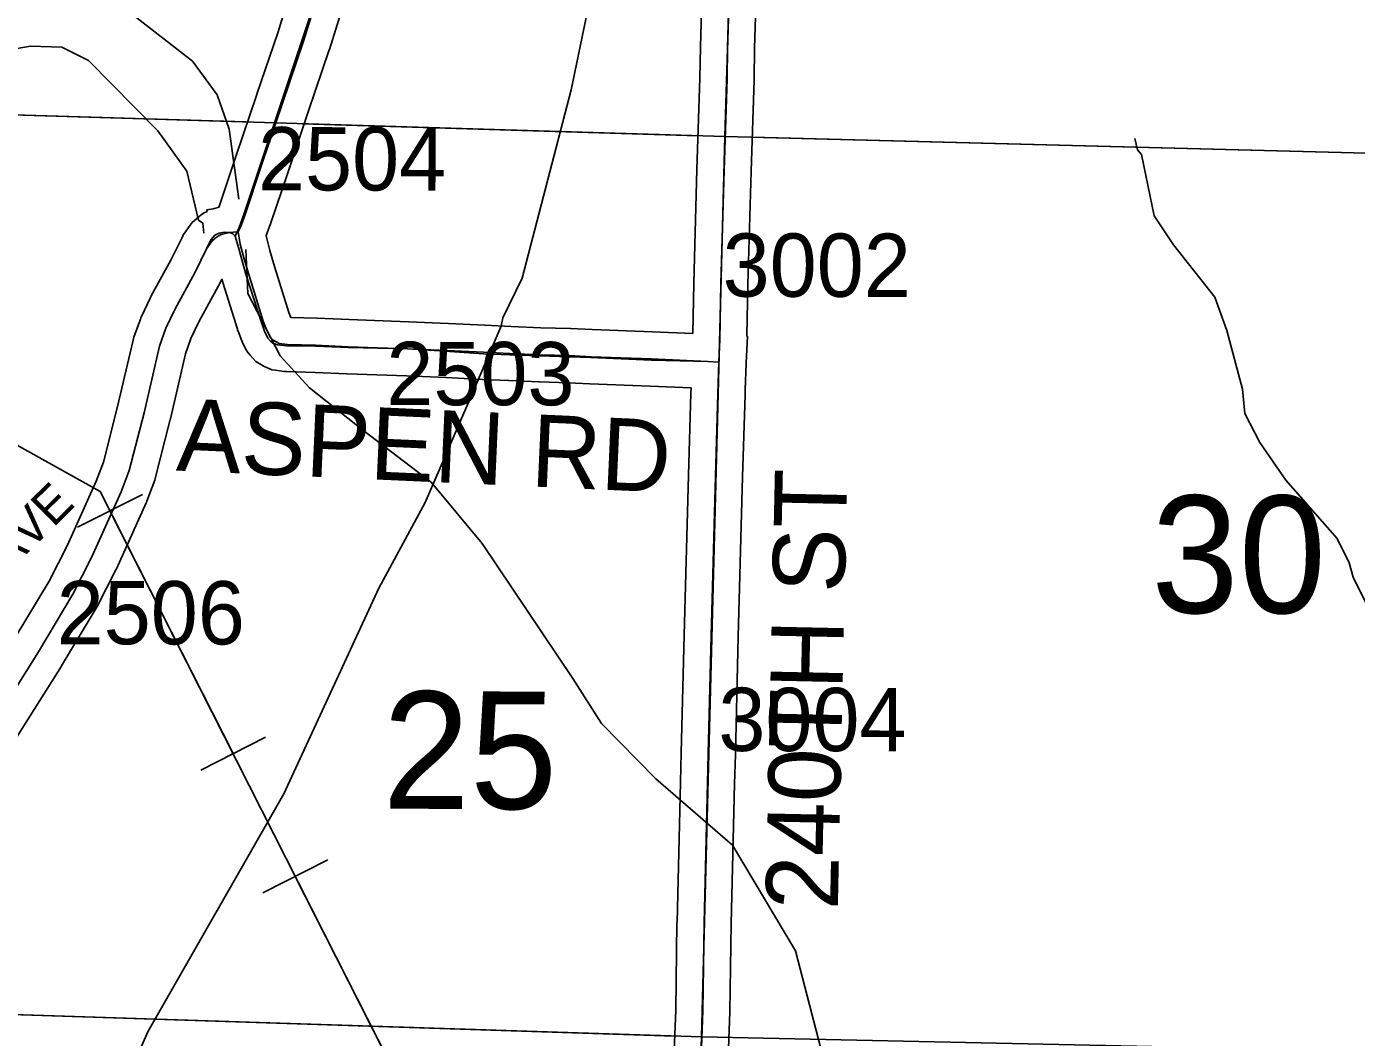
# Model space of a CAD drawing. Extents: x -132.8 to -73.3, y -60 to -26.
# Drawn here: x -116.845 to -115.373, y -55.44 to -54.321 of the extents above; entities that cross this region are included whole.
import ezdxf

# ---------------------------------------------------------------- set-up
doc = ezdxf.new("R2010")
doc.units = 0
for name, color, linetype in [('tdCoHydroRiver', 7, 'Continuous'), ('tdCoPipe', 7, 'Continuous'), ('tdCoRRCL', 7, 'Continuous'), ('tdCoSecRdNmbr', 7, 'Continuous'), ('tdCoSecRdTxt', 7, 'Continuous'), ('tdCoSecRteBand', 7, 'Continuous'), ('tdCoSecRteCL', 7, 'Continuous'), ('tdCoSectLine', 7, 'Continuous'), ('tdCoSectLinePart', 7, 'Continuous'), ('tdCoSectNmbr', 7, 'Continuous'), ('tdCoSurfAsphalt', 7, 'Continuous'), ('tdCoSurfGravel', 7, 'Continuous'), ('tdCoTwpBndryShd', 7, 'Continuous')]:
    doc.layers.add(name, color=color, linetype=linetype)

msp = doc.modelspace()

# ---------------------------------------------------------------- linework, layer by layer
at = {"layer": 'tdCoHydroRiver'}
for points in [[(-116.2762, -53.9828), (-116.2765, -53.9939), (-116.2719, -53.9987), (-116.2692, -54.0177), (-116.2646, -54.0226), (-116.2509, -54.105), (-116.2463, -54.1114), (-116.2384, -54.1731), (-116.2338, -54.178), (-116.2243, -54.2398), (-116.2262, -54.3123), (-116.2424, -54.3908), (-116.2966, -54.5992), (-116.3182, -54.6429), (-116.32, -54.6523), (-116.3553, -54.735), (-116.4039, -54.8474), (-116.4552, -54.9423), (-116.5604, -55.17), (-116.7107, -55.4328), (-116.7224, -55.4593)], [(-116.6489, -54.5492), (-116.6502, -54.5382), (-116.6548, -54.5349), (-116.6677, -54.4809), (-116.6997, -54.4359), (-116.7766, -54.3582), (-116.8062, -54.3433), (-116.8409, -54.3424), (-116.982, -54.3672), (-117.0585, -54.3936), (-117.1383, -54.4295), (-117.159, -54.4368), (-117.2551, -54.4342)], [(-115.1864, -55.1387), (-115.221, -55.1347), (-115.2539, -55.1228), (-115.2725, -55.1097), (-115.297, -55.0807), (-115.3084, -55.0331), (-115.3144, -55.0187), (-115.3603, -54.9639), (-115.3768, -54.9303), (-115.3812, -54.9144), (-115.3947, -54.8873), (-115.4515, -54.8227), (-115.4804, -54.781), (-115.4969, -54.749), (-115.4994, -54.7221), (-115.5167, -54.657), (-115.53, -54.6203), (-115.5759, -54.5624), (-115.5972, -54.5303), (-115.6112, -54.4621), (-115.6158, -54.4572), (-115.6187, -54.4445)]]:
    msp.add_lwpolyline(points, dxfattribs=at)
at = {"layer": 'tdCoPipe'}
for p, q in [((-116.7169, -54.8385), (-116.7888, -54.8749)), ((-116.5806, -55.1073), (-116.6524, -55.1437)), ((-116.5118, -55.243), (-116.5838, -55.2795))]:
    msp.add_line(p, q, dxfattribs=at)
for points in [[(-115.7327, -56.7093), (-116.3792, -55.5939), (-116.7637, -54.8353), (-118.1151, -54.0815), (-118.6092, -53.8056), (-119.7966, -53.496), (-120.031, -53.2709)], [(-116.6166, -55.1255), (-116.7528, -54.8567)], [(-116.4115, -55.5301), (-116.5478, -55.2613)]]:
    msp.add_lwpolyline(points, dxfattribs=at)
at = {"layer": 'tdCoRRCL'}
for points in [[(-117.7743, -53.0804), (-117.6699, -53.3151), (-117.6198, -53.3905), (-117.4718, -53.5238), (-117.421, -53.5756), (-117.4, -53.6156), (-117.379, -53.7218), (-117.416, -53.9307), (-117.4181, -54.0111), (-117.3859, -54.1067), (-117.3433, -54.1677), (-117.2827, -54.2056), (-117.2233, -54.2292), (-116.8722, -54.2637), (-116.7827, -54.2802), (-116.7328, -54.3036), (-116.6616, -54.3591), (-116.6342, -54.3961), (-116.621, -54.4343), (-116.6103, -54.5119)], [(-116.6023, -54.5673), (-116.6004, -54.6163), (-116.5643, -54.6851), (-116.5321, -54.7206), (-116.4718, -54.768), (-116.3975, -54.8251), (-116.3409, -54.8929), (-116.2406, -55.0422), (-116.2087, -55.092), (-116.1487, -55.1535), (-116.0638, -55.2267), (-115.9943, -55.3437), (-115.9584, -55.4819), (-115.9294, -55.5821), (-115.9004, -55.6807), (-115.8417, -55.7911), (-115.8098, -55.8393), (-115.7844, -55.8936), (-115.6201, -56.1329), (-115.346, -56.5172), (-115.1794, -56.6996)]]:
    msp.add_lwpolyline(points, dxfattribs=at)
at = {"layer": 'tdCoSecRteBand'}
for points in [[(-116.1079, -54.6606), (-116.1068, -54.6047), (-116.1068, -54.6046), (-116.1068, -54.6044), (-116.1032, -54.4789), (-116.1032, -54.4789), (-116.1032, -54.4788), (-116.0999, -54.3778), (-116.0994, -54.3432), (-116.0993, -54.343), (-116.0993, -54.3428), (-116.0959, -54.2263)], [(-116.0359, -54.2281), (-116.0394, -54.3444), (-116.0399, -54.379), (-116.0399, -54.3793), (-116.04, -54.3795), (-116.0433, -54.4807), (-116.0468, -54.606), (-116.0479, -54.6629), (-116.0478, -54.6629), (-116.0478, -54.6634), (-116.0474, -54.6634), (-116.0488, -54.6931), (-116.0497, -54.7229), (-116.0497, -54.7229), (-116.0499, -54.7282), (-116.0527, -54.8191), (-116.0574, -54.9958), (-116.0606, -55.1263), (-116.0606, -55.1263), (-116.0606, -55.1264), (-116.0616, -55.1589), (-116.0653, -55.3135), (-116.0667, -55.4108), (-116.0667, -55.4111), (-116.0668, -55.4114), (-116.0697, -55.4921)], [(-116.8576, -54.9971), (-116.82, -54.9344), (-116.8001, -54.8955), (-116.768, -54.824), (-116.7601, -54.803), (-116.7443, -54.7411), (-116.7273, -54.6677), (-116.7269, -54.666), (-116.7264, -54.6643), (-116.7192, -54.6444), (-116.7187, -54.6429), (-116.718, -54.6416), (-116.7079, -54.6204), (-116.7076, -54.6196), (-116.7072, -54.6189), (-116.6855, -54.5792), (-116.6727, -54.5534), (-116.6717, -54.5513), (-116.6703, -54.5493), (-116.6641, -54.5406), (-116.662, -54.5376), (-116.6593, -54.5353), (-116.6544, -54.5311), (-116.652, -54.529), (-116.6492, -54.5274), (-116.6453, -54.5253), (-116.6456, -54.5235), (-116.6387, -54.5223), (-116.6376, -54.522), (-116.6331, -54.5208), (-116.6326, -54.5207), (-116.6322, -54.5206), (-116.6315, -54.5187), (-116.6134, -54.4645), (-116.6134, -54.4645), (-116.6134, -54.4645), (-116.5904, -54.3958), (-116.5904, -54.3957), (-116.5904, -54.3956), (-116.5672, -54.3276), (-116.5558, -54.2914)], [(-116.4981, -54.308), (-116.51, -54.3459), (-116.5101, -54.3463), (-116.5103, -54.3466), (-116.5336, -54.4149), (-116.5565, -54.4835), (-116.5748, -54.5381), (-116.5749, -54.5385), (-116.5751, -54.539), (-116.5798, -54.5518), (-116.5792, -54.5552), (-116.5759, -54.5686), (-116.5706, -54.5863), (-116.5548, -54.637), (-116.5526, -54.6427), (-116.5239, -54.6435), (-116.5238, -54.6435), (-116.5236, -54.6435), (-116.488, -54.645), (-116.4225, -54.6474), (-116.4225, -54.6474), (-116.4225, -54.6474), (-116.3784, -54.6492), (-116.3782, -54.6492), (-116.378, -54.6492), (-116.3379, -54.6513), (-116.3088, -54.6526), (-116.2759, -54.6541), (-116.2434, -54.6549), (-116.2431, -54.6549), (-116.2427, -54.655), (-116.2191, -54.6561), (-116.1525, -54.6586), (-116.1524, -54.6586), (-116.1523, -54.6586), (-116.1079, -54.6606)], [(-116.1297, -55.4899), (-116.1267, -55.4096), (-116.1253, -55.3125), (-116.1253, -55.3124), (-116.1252, -55.3122), (-116.1215, -55.1574), (-116.1215, -55.1573), (-116.1215, -55.1572), (-116.1206, -55.1247), (-116.1174, -54.9943), (-116.1174, -54.9943), (-116.1174, -54.9943), (-116.1127, -54.8174), (-116.1127, -54.8174), (-116.1127, -54.8173), (-116.1098, -54.7264), (-116.1097, -54.7206), (-116.1549, -54.7186), (-116.2216, -54.716), (-116.2217, -54.716), (-116.2219, -54.716), (-116.2453, -54.7149), (-116.2776, -54.7141), (-116.2779, -54.7141), (-116.2783, -54.7141), (-116.3115, -54.7126), (-116.3116, -54.7126), (-116.3116, -54.7126), (-116.3408, -54.7112), (-116.3408, -54.7112), (-116.3409, -54.7112), (-116.3809, -54.7091), (-116.4248, -54.7074), (-116.4903, -54.7049), (-116.4904, -54.7049), (-116.4905, -54.7049), (-116.5259, -54.7035), (-116.5572, -54.7026), (-116.5587, -54.7025), (-116.5603, -54.7023), (-116.5695, -54.7011), (-116.5737, -54.7005), (-116.5776, -54.6988), (-116.5812, -54.6972), (-116.5828, -54.6965), (-116.5844, -54.6955), (-116.5876, -54.6936), (-116.5915, -54.6913), (-116.5946, -54.6879), (-116.5978, -54.6843), (-116.6002, -54.6816), (-116.6019, -54.6785), (-116.6053, -54.6721), (-116.6062, -54.6705), (-116.6069, -54.6687), (-116.6111, -54.6577), (-116.6115, -54.6567), (-116.6118, -54.6558), (-116.6279, -54.6039), (-116.628, -54.6037), (-116.628, -54.6035), (-116.629, -54.6003), (-116.632, -54.6064), (-116.6323, -54.6069), (-116.6326, -54.6075), (-116.6541, -54.6469), (-116.6632, -54.666), (-116.6693, -54.6829), (-116.6859, -54.7549), (-116.686, -54.7553), (-116.6861, -54.7556), (-116.7023, -54.8195), (-116.7027, -54.8211), (-116.7033, -54.8227), (-116.7122, -54.8461), (-116.7125, -54.847), (-116.7129, -54.8478), (-116.7457, -54.9208), (-116.746, -54.9215), (-116.7464, -54.9222), (-116.7671, -54.9626), (-116.7675, -54.9635), (-116.7681, -54.9643), (-116.8063, -55.0282), (-116.8064, -55.0285), (-116.8066, -55.0287), (-116.8606, -55.1148)]]:
    msp.add_lwpolyline(points, dxfattribs=at)
at = {"layer": 'tdCoSecRteCL'}
for points in [[(-116.6109, -54.548), (-116.6084, -54.5427), (-116.6032, -54.5286), (-116.585, -54.474), (-116.562, -54.4053), (-116.5387, -54.3369), (-116.5267, -54.299), (-116.5247, -54.2898), (-116.5242, -54.2767), (-116.5261, -54.265), (-116.5308, -54.2522), (-116.5383, -54.2368), (-116.558, -54.2051), (-116.5754, -54.1761), (-116.5827, -54.1616), (-116.5865, -54.1515), (-116.5931, -54.1288), (-116.6022, -54.0918), (-116.6143, -54.0391), (-116.6334, -53.9599), (-116.6404, -53.9275), (-116.6426, -53.9138)], [(-116.0788, -54.692), (-116.078, -54.667), (-116.0768, -54.6053), (-116.0732, -54.4798), (-116.0699, -54.3785), (-116.0694, -54.3437), (-116.0659, -54.2272), (-116.0619, -54.0859), (-116.0581, -53.9692), (-116.0574, -53.9511)], [(-116.886, -55.0989), (-116.832, -55.0128), (-116.7938, -54.9489), (-116.7731, -54.9085), (-116.7403, -54.8355), (-116.7314, -54.8121), (-116.7151, -54.7482), (-116.6981, -54.6745), (-116.691, -54.6545), (-116.6808, -54.6333), (-116.6589, -54.5931), (-116.6458, -54.5667), (-116.6396, -54.5579), (-116.6348, -54.5537), (-116.6299, -54.551), (-116.6253, -54.5498), (-116.6207, -54.5487), (-116.6166, -54.5482), (-116.6111, -54.548), (-116.6109, -54.548)], [(-116.6109, -54.548), (-116.6086, -54.5614), (-116.6048, -54.5765), (-116.5993, -54.595), (-116.5832, -54.6469), (-116.5789, -54.6579), (-116.5754, -54.6643), (-116.5722, -54.6679), (-116.569, -54.6698), (-116.5655, -54.6714), (-116.5563, -54.6726), (-116.5248, -54.6735), (-116.4892, -54.675), (-116.4237, -54.6774), (-116.3796, -54.6792), (-116.3394, -54.6812), (-116.3102, -54.6826), (-116.2769, -54.6841), (-116.2442, -54.6849), (-116.2204, -54.6861), (-116.1537, -54.6886), (-116.091, -54.6914), (-116.0788, -54.692)], [(-116.1229, -56.2829), (-116.1211, -56.2172), (-116.1165, -56.0456), (-116.1123, -55.9021), (-116.1105, -55.8609), (-116.1056, -55.6826), (-116.1004, -55.5102), (-116.0997, -55.491), (-116.0967, -55.4103), (-116.0953, -55.3129), (-116.0916, -55.1581), (-116.0906, -55.1255), (-116.0874, -54.9951), (-116.0827, -54.8182), (-116.0799, -54.7273), (-116.0788, -54.692)]]:
    msp.add_lwpolyline(points, dxfattribs=at)
at = {"layer": 'tdCoSectLine'}
for points in [[(-116.0724, -54.4424), (-116.042, -53.4425)], [(-117.0554, -54.4124), (-116.0724, -54.4424)], [(-116.0982, -55.4391), (-116.0724, -54.4424)], [(-116.0724, -54.4424), (-115.0922, -54.4677)], [(-117.0994, -55.4066), (-116.0982, -55.4391)], [(-116.0982, -55.4391), (-116.128, -56.4384)], [(-116.0982, -55.4391), (-115.1183, -55.46)]]:
    msp.add_lwpolyline(points, dxfattribs=at)
at = {"layer": 'tdCoSectLinePart'}
for points in [[(-117.0554, -54.4124), (-116.6025, -54.4263)], [(-116.5402, -54.4282), (-116.102, -54.4415)], [(-116.0422, -54.4432), (-115.0922, -54.4677)], [(-117.0994, -55.4066), (-116.128, -55.4381)]]:
    msp.add_lwpolyline(points, dxfattribs=at)
at = {"layer": 'tdCoSurfAsphalt'}
for points in [[(-116.0799, -54.7273), (-116.0788, -54.692), (-116.078, -54.667), (-116.0768, -54.6053), (-116.0732, -54.4798), (-116.0699, -54.3785), (-116.0694, -54.3437), (-116.0659, -54.2272), (-116.0619, -54.0859), (-116.0581, -53.9692), (-116.0574, -53.9511), (-116.0647, -53.9484), (-116.0814, -53.9442), (-116.0967, -53.9419), (-116.1138, -53.9405), (-116.1973, -53.936), (-116.2787, -53.9325), (-116.3314, -53.9303), (-116.4444, -53.9243), (-116.4905, -53.922), (-116.558, -53.9187), (-116.6268, -53.9144), (-116.6426, -53.9138)], [(-116.6109, -54.548), (-116.6084, -54.5427), (-116.6032, -54.5286), (-116.585, -54.474), (-116.562, -54.4053), (-116.5387, -54.3369), (-116.5267, -54.299), (-116.5247, -54.2898), (-116.5242, -54.2767), (-116.5261, -54.265), (-116.5308, -54.2522), (-116.5383, -54.2368), (-116.558, -54.2051), (-116.5754, -54.1761), (-116.5827, -54.1616), (-116.5865, -54.1515), (-116.5931, -54.1288), (-116.6022, -54.0918), (-116.6143, -54.0391), (-116.6334, -53.9599), (-116.6404, -53.9275), (-116.6426, -53.9138)]]:
    msp.add_lwpolyline(points, dxfattribs=at)
at = {"layer": 'tdCoSurfGravel'}
for points in [[(-116.6142, -54.5525), (-116.6099, -54.5432), (-116.6046, -54.5286), (-116.5864, -54.4733), (-116.5632, -54.4051), (-116.5406, -54.3366), (-116.528, -54.2988), (-116.5264, -54.2894), (-116.5259, -54.2769), (-116.5282, -54.2653), (-116.5325, -54.2534), (-116.5397, -54.2376), (-116.5595, -54.2059), (-116.5772, -54.1774), (-116.5849, -54.1632), (-116.589, -54.1527), (-116.5953, -54.1298), (-116.6046, -54.093), (-116.6168, -54.04), (-116.6357, -53.9607), (-116.6429, -53.9278), (-116.6455, -53.9137)], [(-116.0997, -55.491), (-116.0967, -55.4103), (-116.0953, -55.3129), (-116.0916, -55.1581), (-116.0906, -55.1255), (-116.0874, -54.9951), (-116.0827, -54.8182), (-116.0788, -54.692), (-116.078, -54.667), (-116.0768, -54.6053), (-116.0732, -54.4798), (-116.0699, -54.3785), (-116.0694, -54.3437), (-116.0659, -54.2272), (-116.0619, -54.0859), (-116.0581, -53.9692), (-116.0574, -53.9511)], [(-116.886, -55.0989), (-116.832, -55.0128), (-116.7938, -54.9489), (-116.7731, -54.9085), (-116.7403, -54.8355), (-116.7314, -54.8121), (-116.7151, -54.7482), (-116.6981, -54.6745), (-116.691, -54.6545), (-116.6808, -54.6333), (-116.6589, -54.5931), (-116.6458, -54.5667), (-116.6411, -54.5566), (-116.6367, -54.5514), (-116.6318, -54.5494), (-116.6266, -54.5484), (-116.6207, -54.5487), (-116.617, -54.55), (-116.6142, -54.5525)], [(-116.6142, -54.5525), (-116.6106, -54.5651), (-116.6074, -54.5775), (-116.6021, -54.5958), (-116.5855, -54.6473), (-116.5818, -54.6578), (-116.5781, -54.6655), (-116.5752, -54.6688), (-116.5725, -54.6713), (-116.5673, -54.673), (-116.5571, -54.6739), (-116.5255, -54.6743), (-116.4893, -54.676), (-116.4237, -54.6774), (-116.3823, -54.6799), (-116.3395, -54.6829), (-116.3103, -54.6839), (-116.2771, -54.6853), (-116.2444, -54.6861), (-116.2209, -54.6869), (-116.1535, -54.6898), (-116.091, -54.6914), (-116.0788, -54.692)]]:
    msp.add_lwpolyline(points, dxfattribs=at)
at = {"layer": 'tdCoTwpBndryShd'}
msp.add_lwpolyline([(-116.128, -56.4384), (-116.0982, -55.4391), (-116.0724, -54.4424), (-116.042, -53.4425), (-116.0101, -52.4492), (-115.9802, -51.4416), (-115.9494, -50.483), (-115.9254, -49.4919), (-115.9017, -48.4949), (-115.8779, -47.4977), (-115.834, -46.4945), (-115.8159, -45.5058), (-115.7834, -44.5349), (-115.7494, -43.5344), (-115.7226, -42.5378), (-115.6969, -41.5376), (-115.6667, -40.5277)], dxfattribs=at)

# ---------------------------------------------------------------- texts
at = {"layer": 'tdCoSecRdNmbr'}
for s, rotation, p in [('2504', 359.9124, (-116.589, -54.5019)), ('3002', 359.9128, (-116.0748, -54.6196)), ('2503', 359.9125, (-116.447, -54.7396)), ('2506', 359.9122, (-116.8118, -55.0043)), ('3004', 359.9128, (-116.0795, -55.1225))]:
    msp.add_text(s, height=0.07, rotation=rotation, dxfattribs=at).set_placement(p)
at = {"layer": 'tdCoSecRdTxt'}
for s, height, rotation, p in [('ASPEN RD', 0.08, 357.4351, (-116.6801, -54.8121)), ('240TH ST', 0.08, 88.7757, (-115.9473, -55.2989)), ('DUMFRIES AVE', 0.04, 44.6347, (-117.0758, -55.1327))]:
    msp.add_text(s, height=height, rotation=rotation, dxfattribs=at).set_placement(p)
at = {"layer": 'tdCoSectNmbr'}
for s, rotation, p in [('30', 359.9131, (-115.6004, -54.9697)), ('25', 359.9124, (-116.4512, -55.1865))]:
    msp.add_text(s, height=0.13, rotation=rotation, dxfattribs=at).set_placement(p)

doc.saveas('drawing.dxf')
